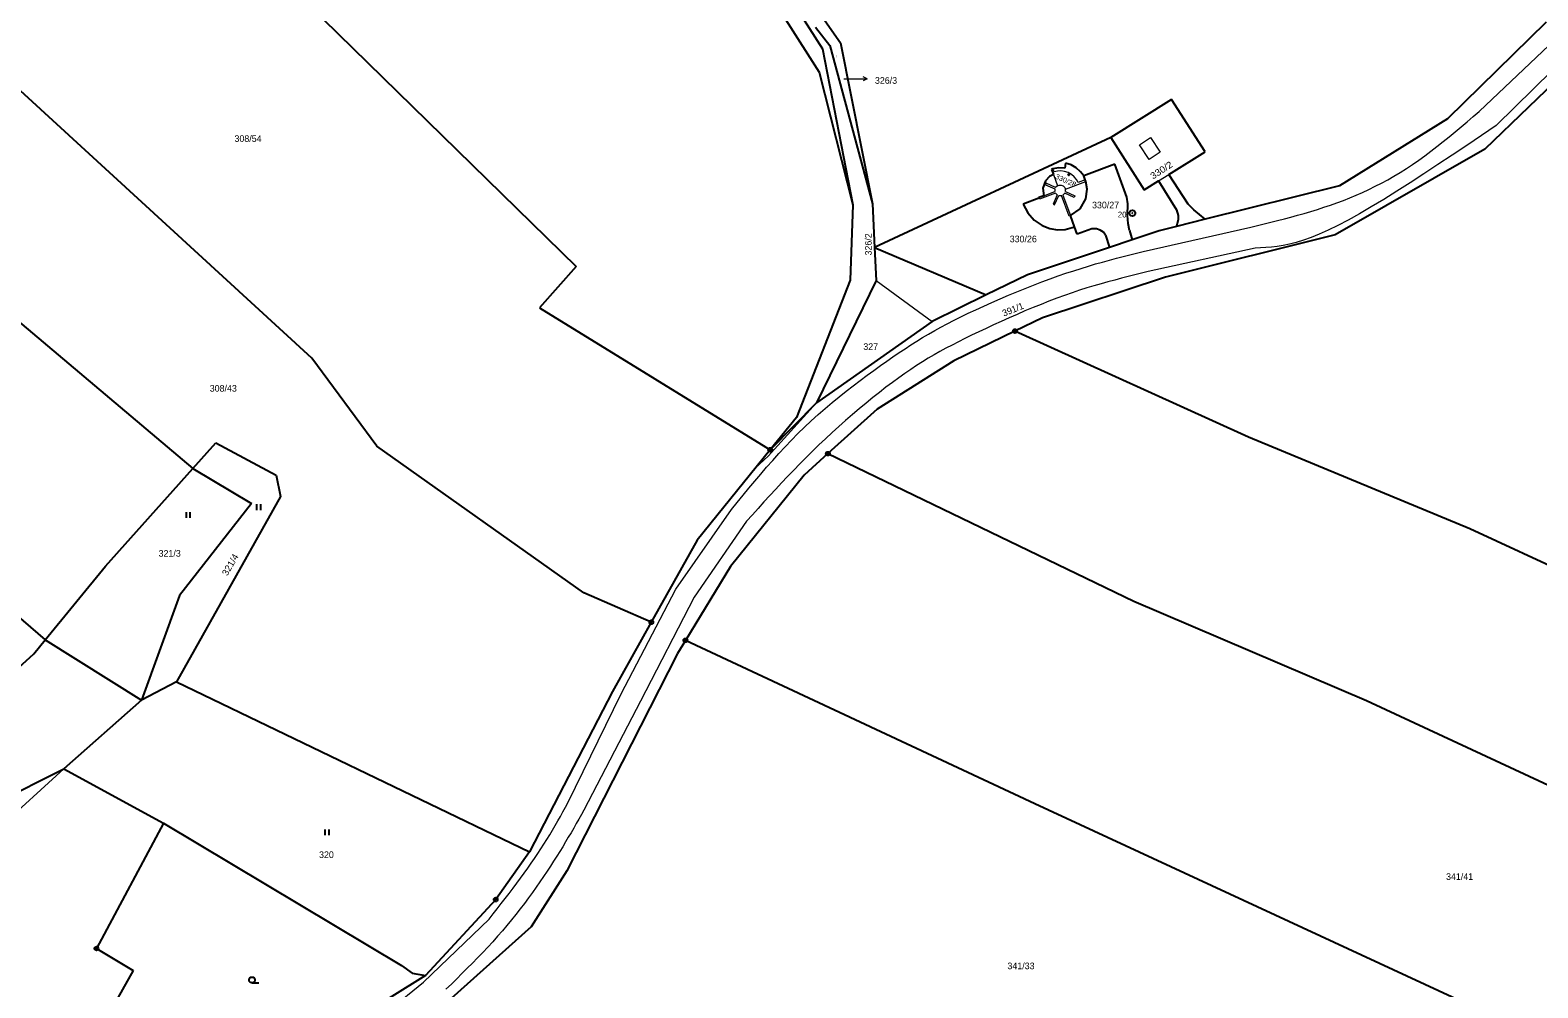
# Model space of a CAD drawing. Extents: x -504006 to -501322, y -1128098 to -1124665.
# Drawn here: x -502339.3 to -501952.3, y -1126399.9 to -1126154.2 of the extents above; entities that cross this region are included whole.
import ezdxf
from ezdxf.enums import TextEntityAlignment as Align

# ---------------------------------------------------------------- set-up
doc = ezdxf.new("R2010")
doc.units = 0
doc.header["$LTSCALE"] = 0.68
for name, color, linetype, lineweight in [('1', 7, 'Continuous', 25), ('13', 7, 'Continuous', 13), ('3', 7, 'Continuous', 25), ('4', 7, 'Continuous', 13), ('5', 7, 'Continuous', 25), ('7', 7, 'Continuous', 13), ('8', 7, 'Continuous', 25)]:
    doc.layers.add(name, color=color, linetype=linetype, lineweight=lineweight)
doc.layers.add('2', color=7, linetype='Continuous')

msp = doc.modelspace()

# ---------------------------------------------------------------- linework, layer by layer
at = {"layer": '1'}
for p, q in [((-502267.06, -1126238.34), (-502376.63, -1126137.93)), ((-502267.99, -1126147.63), (-502199.14, -1126214.86)), ((-502145.36, -1126151.59), (-502136.75, -1126165.01)), ((-502142.61, -1126148.53), (-502135.9, -1126158.99)), ((-502137.15, -1126149.16), (-502131.3, -1126157.5)), ((-502137.69, -1126153.45), (-502134.08, -1126158.11)), ((-501950.18, -1126152.14), (-501975.45, -1126176.97)), ((-502135.9, -1126158.99), (-502128.12, -1126199.06)), ((-502134.08, -1126158.11), (-502123.09, -1126198.77)), ((-502131.3, -1126157.5), (-502123.09, -1126198.77)), ((-501939.97, -1126159.72), (-501965.91, -1126184.76)), ((-502416.62, -1126166.49), (-502297.55, -1126266.63)), ((-502136.75, -1126165.01), (-502128.12, -1126199.06)), ((-502046.36, -1126172.01), (-502061.87, -1126181.73)), ((-502037.67, -1126185.42), (-502046.36, -1126172.01)), ((-501975.45, -1126176.97), (-502003.25, -1126194.13)), ((-502061.87, -1126181.73), (-502122.57, -1126209.98)), ((-502061.87, -1126181.73), (-502053.39, -1126195.17)), ((-502047.04, -1126191.23), (-502037.67, -1126185.42)), ((-501965.91, -1126184.76), (-502004.3, -1126206.75)), ((-502076.77, -1126189.81), (-502077.13, -1126189.96)), ((-502077.13, -1126189.96), (-502076.67, -1126191.24)), ((-502075.28, -1126189.52), (-502076.77, -1126189.81)), ((-502073.76, -1126189.62), (-502075.28, -1126189.52)), ((-502073.53, -1126188.36), (-502073.76, -1126189.62)), ((-502072.1, -1126188.77), (-502073.53, -1126188.36)), ((-502070.78, -1126189.53), (-502072.1, -1126188.77)), ((-502069.67, -1126190.54), (-502070.78, -1126189.53)), ((-502068.88, -1126191.62), (-502069.67, -1126190.54)), ((-502060.89, -1126188.6), (-502068.88, -1126191.62)), ((-502057.81, -1126197.02), (-502060.89, -1126188.6)), ((-502078.68, -1126192.85), (-502079.36, -1126194.71)), ((-502077.63, -1126191.74), (-502078.68, -1126192.85)), ((-502076.67, -1126191.24), (-502077.63, -1126191.74)), ((-502068.46, -1126192.62), (-502068.88, -1126191.62)), ((-502068.29, -1126193), (-502068.46, -1126192.62)), ((-502067.96, -1126195.01), (-502068.29, -1126193)), ((-502042.05, -1126198.86), (-502047.04, -1126191.23)), ((-502003.25, -1126194.13), (-502037.72, -1126202.72)), ((-502080.38, -1126197.3), (-502084.38, -1126198.83)), ((-502079.14, -1126196.67), (-502080.38, -1126197.17)), ((-502080.38, -1126197.17), (-502080.38, -1126197.3)), ((-502079.36, -1126194.71), (-502079.14, -1126196.67)), ((-502069.82, -1126200.05), (-502068.31, -1126197.46)), ((-502068.31, -1126197.46), (-502067.96, -1126195.01)), ((-502057.56, -1126198.77), (-502057.81, -1126197.02)), ((-502128.12, -1126199.06), (-502128.81, -1126218.35)), ((-502123.09, -1126198.77), (-502122.57, -1126209.98)), ((-502084.38, -1126198.83), (-502083.26, -1126201.06)), ((-502083.26, -1126201.06), (-502081.59, -1126202.91)), ((-502072.23, -1126201.79), (-502069.82, -1126200.05)), ((-502071.24, -1126204.68), (-502072.23, -1126201.79)), ((-502057.61, -1126201.78), (-502057.56, -1126198.77)), ((-502057.47, -1126203.79), (-502057.61, -1126201.78)), ((-502045.08, -1126200.32), (-502044.59, -1126201.77)), ((-502044.59, -1126201.77), (-502044.66, -1126202.76)), ((-502040.63, -1126200.34), (-502042.05, -1126198.86)), ((-502037.72, -1126202.72), (-502040.63, -1126200.34)), ((-502081.59, -1126202.91), (-502079.52, -1126204.35)), ((-502079.52, -1126204.35), (-502077.61, -1126205.06)), ((-502077.61, -1126205.06), (-502075.64, -1126205.42)), ((-502075.64, -1126205.42), (-502073.62, -1126205.35)), ((-502073.62, -1126205.35), (-502071.24, -1126204.68)), ((-502070.55, -1126206.55), (-502071.24, -1126204.68)), ((-502066.8, -1126205.19), (-502070.55, -1126206.55)), ((-502065.62, -1126205.16), (-502066.8, -1126205.19)), ((-502064.66, -1126205.48), (-502065.62, -1126205.16)), ((-502063.81, -1126205.99), (-502064.66, -1126205.48)), ((-502063.25, -1126206.79), (-502063.81, -1126205.99)), ((-502057.12, -1126205.57), (-502057.47, -1126203.79)), ((-502057.12, -1126205.57), (-502056.41, -1126207.97)), ((-502049.53, -1126205.67), (-502056.41, -1126207.97)), ((-502045.09, -1126204.55), (-502049.53, -1126205.67)), ((-502037.72, -1126202.72), (-502045.09, -1126204.55)), ((-502044.66, -1126202.76), (-502045.09, -1126204.55)), ((-502063.25, -1126206.79), (-502062.29, -1126209.93)), ((-502056.41, -1126207.97), (-502062.29, -1126209.93)), ((-502004.3, -1126206.75), (-502047.9, -1126217.56)), ((-502122.57, -1126209.98), (-502122.18, -1126218.47)), ((-502122.57, -1126209.98), (-502093.89, -1126222.14)), ((-502062.29, -1126209.93), (-502083.31, -1126216.95)), ((-502199.14, -1126214.86), (-502208.56, -1126225.48)), ((-502083.31, -1126216.95), (-502093.89, -1126222.14)), ((-502047.9, -1126217.56), (-502079.49, -1126228.01)), ((-502128.81, -1126218.35), (-502142.59, -1126253.6)), ((-502122.18, -1126218.47), (-502137.5, -1126249.81)), ((-502093.89, -1126222.14), (-502107.81, -1126228.96)), ((-502208.56, -1126225.48), (-502149.35, -1126261.86)), ((-502107.81, -1126228.96), (-502137.5, -1126249.81)), ((-502079.49, -1126228.01), (-502086.52, -1126231.41)), ((-502086.52, -1126231.41), (-502102.24, -1126239.03)), ((-502026.54, -1126258.64), (-502086.52, -1126231.41)), ((-502250.32, -1126260.95), (-502267.06, -1126238.34)), ((-502102.24, -1126239.03), (-502121.91, -1126251.48)), ((-502137.5, -1126249.81), (-502149.35, -1126261.86)), ((-502121.91, -1126251.48), (-502134.55, -1126262.85)), ((-502142.59, -1126253.6), (-502149.35, -1126261.86)), ((-502297.55, -1126266.63), (-502291.67, -1126260.08)), ((-502291.67, -1126260.08), (-502276.15, -1126268.36)), ((-501969.71, -1126282.18), (-502026.54, -1126258.64)), ((-502197.19, -1126298.58), (-502250.32, -1126260.95)), ((-502149.35, -1126261.86), (-502168.11, -1126285.04)), ((-502134.55, -1126262.85), (-502140.68, -1126268.36)), ((-502134.55, -1126262.85), (-502056, -1126300.74)), ((-502320, -1126291.68), (-502297.55, -1126266.63)), ((-502297.55, -1126266.63), (-502282.52, -1126275.66)), ((-502276.15, -1126268.36), (-502275.03, -1126273.85)), ((-502140.68, -1126268.36), (-502159.59, -1126291.81)), ((-502275.03, -1126273.85), (-502301.74, -1126321.42)), ((-502282.52, -1126275.66), (-502300.99, -1126299.23)), ((-502371.39, -1126279.76), (-502335.48, -1126310.66)), ((-501870.92, -1126327.95), (-501969.71, -1126282.18)), ((-502168.11, -1126285.04), (-502179.88, -1126306.1)), ((-502335.48, -1126310.66), (-502320, -1126291.68)), ((-502159.59, -1126291.81), (-502171.13, -1126310.75)), ((-502179.88, -1126306.1), (-502197.19, -1126298.58)), ((-502300.99, -1126299.23), (-502310.79, -1126326.11)), ((-502056, -1126300.74), (-501996.25, -1126326.18)), ((-502179.88, -1126306.1), (-502189.81, -1126323.88)), ((-502353.36, -1126327.7), (-502338.37, -1126314.2)), ((-502338.37, -1126314.2), (-502335.48, -1126310.66)), ((-502335.48, -1126310.66), (-502310.79, -1126326.11)), ((-502173.18, -1126314.11), (-502201.59, -1126369.88)), ((-502171.13, -1126310.75), (-502173.18, -1126314.11)), ((-502081.42, -1126352.69), (-502171.13, -1126310.75)), ((-502301.74, -1126321.42), (-502310.79, -1126326.11)), ((-502301.74, -1126321.42), (-502211.13, -1126365)), ((-502189.81, -1126323.88), (-502211.13, -1126365)), ((-502310.79, -1126326.11), (-502330.66, -1126343.74)), ((-501996.25, -1126326.18), (-501888.48, -1126376.43)), ((-502351.57, -1126354.18), (-502330.66, -1126343.74)), ((-502330.66, -1126343.74), (-502305.09, -1126357.63)), ((-501962.67, -1126407.69), (-502081.42, -1126352.69)), ((-502305.09, -1126357.63), (-502322.32, -1126389.81)), ((-502305.09, -1126357.63), (-502244, -1126394.15)), ((-502211.13, -1126365), (-502219.82, -1126377.25)), ((-502201.59, -1126369.88), (-502210.7, -1126384.25)), ((-502219.82, -1126377.25), (-502237.81, -1126396.7)), ((-502210.7, -1126384.25), (-502231.23, -1126402.64)), ((-502322.32, -1126389.81), (-502312.89, -1126395.43)), ((-502312.89, -1126395.43), (-502336.64, -1126437.76)), ((-502244, -1126394.15), (-502241.24, -1126396.1)), ((-502237.81, -1126396.7), (-502255.14, -1126407.52)), ((-502241.24, -1126396.1), (-502237.81, -1126396.7))]:
    msp.add_line(p, q, dxfattribs=at)
msp.add_lwpolyline([(-502053.39, -1126195.17), (-502049.66, -1126192.86), (-502045.08, -1126200.32)], dxfattribs=at)
at = {"layer": '13'}
msp.add_lwpolyline([(-502153.1, -1126266.5), (-502149.88, -1126263.46), (-502137.5, -1126249.81), (-502149.35, -1126261.86)], close=True, dxfattribs=at)
at = {"layer": '3'}
for p, q in [((-502299.221, -1126279.36), (-502299.221, -1126277.86)), ((-502298.22, -1126279.36), (-502298.22, -1126277.86)), ((-502281.161, -1126277.33), (-502281.161, -1126275.83)), ((-502280.16, -1126277.33), (-502280.16, -1126275.83)), ((-502263.591, -1126360.77), (-502263.591, -1126359.27)), ((-502262.59, -1126360.77), (-502262.59, -1126359.27)), ((-502282.393, -1126398.62), (-502280.643, -1126398.62))]:
    msp.add_line(p, q, dxfattribs=at)
msp.add_circle((-502282.3929, -1126397.8698), 0.75, dxfattribs=at)
at = {"layer": '4'}
for p, q in [((-501967.34, -1126175.07), (-501946.14, -1126154.97)), ((-501941.7, -1126157.71), (-501962.97, -1126178.69)), ((-502054.51, -1126183.61), (-502051.69, -1126181.77)), ((-502051.69, -1126181.77), (-502049.24, -1126185.52)), ((-502052.05, -1126187.38), (-502054.51, -1126183.61)), ((-502049.24, -1126185.52), (-502052.05, -1126187.38)), ((-502076.47, -1126190.53), (-502076.77, -1126189.81)), ((-502075.62, -1126190.34), (-502076.47, -1126190.53)), ((-502074.71, -1126190.31), (-502075.62, -1126190.34)), ((-502073.78, -1126190.44), (-502074.71, -1126190.31)), ((-502072.87, -1126190.75), (-502073.78, -1126190.44)), ((-502078.48, -1126193.48), (-502078.66, -1126193.86)), ((-502078.66, -1126193.86), (-502076.26, -1126194.92)), ((-502076.08, -1126194.55), (-502078.48, -1126193.48)), ((-502076.67, -1126191.24), (-502075.62, -1126194.14)), ((-502075.62, -1126194.14), (-502076.08, -1126194.55)), ((-502075.62, -1126194.14), (-502075.17, -1126193.96)), ((-502075.17, -1126193.96), (-502074.64, -1126193.96)), ((-502074.64, -1126193.96), (-502074.13, -1126194.18)), ((-502074.13, -1126194.18), (-502073.76, -1126194.56)), ((-502073.58, -1126195), (-502068.29, -1126193)), ((-502072.04, -1126191.23), (-502072.87, -1126190.75)), ((-502071.33, -1126191.84), (-502072.04, -1126191.23)), ((-502070.75, -1126192.55), (-502071.33, -1126191.84)), ((-502070.33, -1126193.31), (-502070.75, -1126192.55)), ((-502068.46, -1126192.62), (-502070.33, -1126193.31)), ((-502049.66, -1126192.86), (-502047.04, -1126191.23)), ((-502080.22, -1126197.55), (-502080.38, -1126197.17)), ((-502076.1, -1126195.99), (-502080.22, -1126197.55)), ((-502079.14, -1126196.67), (-502076.26, -1126195.61)), ((-502075.68, -1126196.47), (-502076.73, -1126198.86)), ((-502076.34, -1126199.04), (-502075.29, -1126196.64)), ((-502076.26, -1126194.92), (-502076.26, -1126195.61)), ((-502076.1, -1126195.99), (-502075.68, -1126196.47)), ((-502075.29, -1126196.64), (-502074.6, -1126196.66)), ((-502072.62, -1126201.91), (-502074.6, -1126196.66)), ((-502074.2, -1126196.51), (-502073.75, -1126196.03)), ((-502074.2, -1126196.51), (-502072.23, -1126201.79)), ((-502073.76, -1126194.56), (-502073.58, -1126195)), ((-502071.36, -1126197.14), (-502073.75, -1126196.03)), ((-502073.54, -1126195.61), (-502073.58, -1126195)), ((-502073.54, -1126195.61), (-502071.16, -1126196.73)), ((-502071.16, -1126196.73), (-502071.36, -1126197.14)), ((-502076.73, -1126198.86), (-502076.34, -1126199.04)), ((-502072.23, -1126201.79), (-502072.62, -1126201.91)), ((-502053.59, -1126210.98), (-502025.95, -1126204.77)), ((-502024.88, -1126210.14), (-502052.35, -1126216.16)), ((-502122.18, -1126218.47), (-502107.81, -1126228.96)), ((-502173.62, -1126297.59), (-502159.33, -1126277.17)), ((-502155.41, -1126280.2), (-502168.91, -1126299.7)), ((-502187.6, -1126324.48), (-502173.62, -1126297.59)), ((-502168.91, -1126299.7), (-502182.65, -1126326.34)), ((-502201.27, -1126352.41), (-502187.6, -1126324.48)), ((-502182.65, -1126326.34), (-502197.16, -1126354.31)), ((-502347.44, -1126358.94), (-502330.66, -1126343.74)), ((-502238.38, -1126398.45), (-502221.51, -1126382.26)), ((-502247.02, -1126405.44), (-502238.38, -1126398.45))]:
    msp.add_line(p, q, dxfattribs=at)
for points in [[(-502025.95, -1126204.77), (-502024.239, -1126204.352), (-502022.508, -1126203.926), (-502020.799, -1126203.501), (-502019.092, -1126203.069), (-502017.368, -1126202.623), (-502015.667, -1126202.171), (-502013.97, -1126201.706), (-502012.258, -1126201.22), (-502010.571, -1126200.721), (-502008.89, -1126200.203), (-502007.196, -1126199.655), (-502005.53, -1126199.09), (-502003.872, -1126198.498), (-502002.201, -1126197.87), (-502000.559, -1126197.219), (-501998.923, -1126196.537), (-501997.276, -1126195.812), (-501995.656, -1126195.061), (-501994.043, -1126194.272), (-501992.417, -1126193.434), (-501990.818, -1126192.566), (-501989.225, -1126191.656), (-501987.62, -1126190.69), (-501986.04, -1126189.69), (-501984.466, -1126188.643), (-501982.879, -1126187.54), (-501981.316, -1126186.41), (-501979.758, -1126185.245), (-501978.185, -1126184.034), (-501976.634, -1126182.809), (-501975.087, -1126181.561), (-501973.523, -1126180.277), (-501971.98, -1126178.993), (-501970.439, -1126177.697), (-501968.88, -1126176.378), (-501967.34, -1126175.07)], [(-501962.97, -1126178.69), (-501966.742, -1126181.226), (-501970.543, -1126183.774), (-501974.265, -1126186.258), (-501977.937, -1126188.691), (-501981.585, -1126191.084), (-501985.106, -1126193.362), (-501988.527, -1126195.538), (-501991.87, -1126197.619), (-501995.039, -1126199.538), (-501998.058, -1126201.303), (-502000.943, -1126202.915), (-502003.61, -1126204.32), (-502006.082, -1126205.526), (-502008.397, -1126206.555), (-502010.516, -1126207.4), (-502012.486, -1126208.092), (-502014.343, -1126208.653), (-502016.061, -1126209.087), (-502017.679, -1126209.419), (-502019.231, -1126209.668), (-502020.697, -1126209.846), (-502022.114, -1126209.972), (-502023.514, -1126210.065), (-502024.88, -1126210.14)], [(-502159.33, -1126277.17), (-502157.844, -1126275.361), (-502156.338, -1126273.533), (-502154.843, -1126271.731), (-502153.339, -1126269.937), (-502151.804, -1126268.13), (-502150.271, -1126266.358), (-502148.721, -1126264.599), (-502147.129, -1126262.837), (-502145.532, -1126261.115), (-502143.907, -1126259.415), (-502142.23, -1126257.719), (-502140.54, -1126256.07), (-502138.814, -1126254.45), (-502137.037, -1126252.841), (-502135.259, -1126251.286), (-502133.467, -1126249.766), (-502131.645, -1126248.266), (-502129.846, -1126246.823), (-502128.054, -1126245.423), (-502126.255, -1126244.051), (-502124.501, -1126242.742), (-502122.777, -1126241.481), (-502121.071, -1126240.257), (-502119.43, -1126239.1), (-502117.838, -1126237.997), (-502116.269, -1126236.931), (-502114.748, -1126235.921), (-502113.244, -1126234.948), (-502111.728, -1126233.995), (-502110.224, -1126233.078), (-502108.702, -1126232.181), (-502107.133, -1126231.286), (-502105.54, -1126230.409), (-502103.896, -1126229.533), (-502102.166, -1126228.642), (-502100.38, -1126227.75), (-502098.511, -1126226.844), (-502096.541, -1126225.914), (-502094.531, -1126224.99), (-502092.469, -1126224.066), (-502090.341, -1126223.135), (-502088.209, -1126222.225), (-502086.061, -1126221.33), (-502083.882, -1126220.446), (-502081.735, -1126219.599), (-502079.607, -1126218.784), (-502077.485, -1126217.996), (-502075.43, -1126217.26), (-502073.427, -1126216.57), (-502071.449, -1126215.917), (-502069.541, -1126215.311), (-502067.673, -1126214.741), (-502065.82, -1126214.197), (-502064.02, -1126213.687), (-502062.247, -1126213.201), (-502060.476, -1126212.73), (-502058.744, -1126212.28), (-502057.025, -1126211.841), (-502055.295, -1126211.406), (-502053.59, -1126210.98)], [(-502052.35, -1126216.16), (-502054.041, -1126216.571), (-502055.756, -1126216.991), (-502057.459, -1126217.414), (-502059.172, -1126217.849), (-502060.92, -1126218.305), (-502062.667, -1126218.776), (-502064.435, -1126219.271), (-502066.251, -1126219.8), (-502068.074, -1126220.355), (-502069.93, -1126220.946), (-502071.846, -1126221.585), (-502073.78, -1126222.26), (-502075.755, -1126222.981), (-502077.789, -1126223.754), (-502079.823, -1126224.554), (-502081.871, -1126225.385), (-502083.947, -1126226.251), (-502085.994, -1126227.125), (-502088.024, -1126228.013), (-502090.054, -1126228.919), (-502092.023, -1126229.816), (-502093.947, -1126230.709), (-502095.837, -1126231.603), (-502097.64, -1126232.47), (-502099.371, -1126233.318), (-502101.056, -1126234.162), (-502102.665, -1126234.99), (-502104.23, -1126235.818), (-502105.777, -1126236.665), (-502107.281, -1126237.518), (-502108.769, -1126238.394), (-502110.27, -1126239.312), (-502111.758, -1126240.257), (-502113.261, -1126241.248), (-502114.807, -1126242.305), (-502116.37, -1126243.41), (-502117.975, -1126244.581), (-502119.638, -1126245.83), (-502121.314, -1126247.123), (-502123.016, -1126248.469), (-502124.758, -1126249.88), (-502126.492, -1126251.317), (-502128.233, -1126252.792), (-502129.996, -1126254.318), (-502131.732, -1126255.854), (-502133.455, -1126257.414), (-502135.18, -1126259.01), (-502136.86, -1126260.6), (-502138.51, -1126262.199), (-502140.151, -1126263.824), (-502141.746, -1126265.437), (-502143.317, -1126267.056), (-502144.886, -1126268.7), (-502146.418, -1126270.328), (-502147.935, -1126271.961), (-502149.457, -1126273.617), (-502150.95, -1126275.255), (-502152.435, -1126276.896), (-502153.933, -1126278.557), (-502155.41, -1126280.2)], [(-502221.51, -1126382.26), (-502220.478, -1126380.942), (-502219.435, -1126379.61), (-502218.411, -1126378.296), (-502217.394, -1126376.985), (-502216.377, -1126375.662), (-502215.384, -1126374.361), (-502214.408, -1126373.066), (-502213.439, -1126371.764), (-502212.503, -1126370.486), (-502211.591, -1126369.218), (-502210.696, -1126367.945), (-502209.84, -1126366.7), (-502209.016, -1126365.468), (-502208.211, -1126364.233), (-502207.443, -1126363.023), (-502206.699, -1126361.824), (-502205.968, -1126360.619), (-502205.264, -1126359.436), (-502204.577, -1126358.26), (-502203.894, -1126357.075), (-502203.231, -1126355.908), (-502202.575, -1126354.745), (-502201.917, -1126353.57), (-502201.27, -1126352.41)], [(-502197.16, -1126354.31), (-502197.813, -1126355.455), (-502198.476, -1126356.615), (-502199.137, -1126357.766), (-502199.806, -1126358.923), (-502200.493, -1126360.102), (-502201.186, -1126361.278), (-502201.894, -1126362.467), (-502202.629, -1126363.684), (-502203.376, -1126364.904), (-502204.147, -1126366.143), (-502204.954, -1126367.417), (-502205.78, -1126368.7), (-502206.637, -1126370.007), (-502207.536, -1126371.352), (-502208.455, -1126372.7), (-502209.405, -1126374.065), (-502210.397, -1126375.461), (-502211.408, -1126376.85), (-502212.448, -1126378.248), (-502213.532, -1126379.667), (-502214.632, -1126381.073), (-502215.761, -1126382.477), (-502216.933, -1126383.895), (-502218.12, -1126385.29), (-502219.335, -1126386.676), (-502220.592, -1126388.071), (-502221.857, -1126389.442), (-502223.143, -1126390.806), (-502224.465, -1126392.18), (-502225.787, -1126393.532), (-502227.124, -1126394.88), (-502228.488, -1126396.24), (-502229.846, -1126397.581), (-502231.211, -1126398.92), (-502232.598, -1126400.273)]]:
    msp.add_lwpolyline(points, dxfattribs=at)
at = {"layer": '5'}
msp.add_circle((-502072.6968, -1126191.2992), 0.175, dxfattribs=at)
at = {"layer": '7'}
msp.add_line((-502124.469, -1126166.68), (-502125.47, -1126166.179), dxfattribs=at)
msp.add_lwpolyline([(-502130.47, -1126166.68), (-502127.47, -1126166.68), (-502124.469, -1126166.68), (-502125.47, -1126167.181)], dxfattribs=at)
at = {"layer": '8'}
for centre, radius in [((-502056.39, -1126201.1498), 0.75), ((-502056.39, -1126201.1498), 0.03), ((-502086.52, -1126231.4099), 0.5), ((-502086.52, -1126231.4099), 0.0303), ((-502149.35, -1126261.8599), 0.5), ((-502149.35, -1126261.8599), 0.0303), ((-502134.55, -1126262.8499), 0.5), ((-502134.55, -1126262.8499), 0.0303), ((-502179.88, -1126306.0999), 0.5), ((-502179.88, -1126306.0999), 0.0303), ((-502171.13, -1126310.7499), 0.5), ((-502171.13, -1126310.7499), 0.0303), ((-502219.82, -1126377.2499), 0.5), ((-502219.82, -1126377.2499), 0.0303), ((-502322.32, -1126389.8099), 0.5), ((-502322.32, -1126389.8099), 0.0303)]:
    msp.add_circle(centre, radius, dxfattribs=at)

# ---------------------------------------------------------------- texts
at = {"layer": '2'}
for s, height, rotation, p in [('326/3', 0.2, 284, (-502132.4651, -1126160.9143)), ('326/2', 1.7, 90, (-502123.305, -1126209.17)), ('391/1', 1.7, 22, (-502086.7284, -1126226.6481))]:
    msp.add_text(s, height=height, rotation=rotation, dxfattribs=at).set_placement(p, align=Align.CENTER)
for s, p in [('326/3', (-502122.47, -1126167.962)), ('308/54', (-502286.88, -1126182.875)), ('341/41', (-501975.85, -1126372.195))]:
    msp.add_text(s, height=1.7, dxfattribs=at).set_placement(p)
at = {"layer": '2', "width": 1.1}
msp.add_text('330/2', height=1.7, rotation=33, dxfattribs=at).set_placement((-502051.098, -1126192.546))
at = {"layer": '2', "width": 1.05}
for s, height, rotation, p in [('330/28', 1.309, 336, (-502073.7572, -1126193.3689)), ('321/4', 1.7, 60, (-502287.246, -1126291.7755))]:
    msp.add_text(s, height=height, rotation=rotation, dxfattribs=at).set_placement(p, align=Align.CENTER)
at = {"layer": '2'}
for s, p in [('330/27', (-502063.26, -1126199.925)), ('330/26', (-502084.39, -1126208.625)), ('327', (-502123.559, -1126236.235)), ('308/43', (-502289.76, -1126246.945)), ('321/3', (-502303.52, -1126289.285)), ('320', (-502263.279, -1126366.595)), ('341/33', (-502084.97, -1126395.115))]:
    msp.add_text(s, height=1.7, dxfattribs=at).set_placement(p, align=Align.CENTER)
at = {"layer": '8'}
msp.add_text('20', height=1.5, dxfattribs=at).set_placement((-502057.889, -1126202.267), align=Align.RIGHT)

doc.saveas('drawing.dxf')
